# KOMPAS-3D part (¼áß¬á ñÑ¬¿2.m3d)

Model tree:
1. Эскиз:1
2. Операция выдавливания:24
     Толщина стенки 2 = 10; Расстояние 1 = 0.6
3. Эскиз:22
4. Операция выдавливания:25
     Толщина стенки 1 = 6; Толщина стенки 2 = 6; Расстояние 1 = 0.6
5. Эскиз:23
6. Операция выдавливания:26
     Толщина стенки 1 = 6; Толщина стенки 2 = 6; Расстояние 1 = 0.6
7. Эскиз:24
8. Операция выдавливания:27
     Толщина стенки 1 = 6; Толщина стенки 2 = 6; Расстояние 1 = 0.6
9. Эскиз:25
10. Вырезать элемент выдавливания:10
     Расстояние 1 = 10
